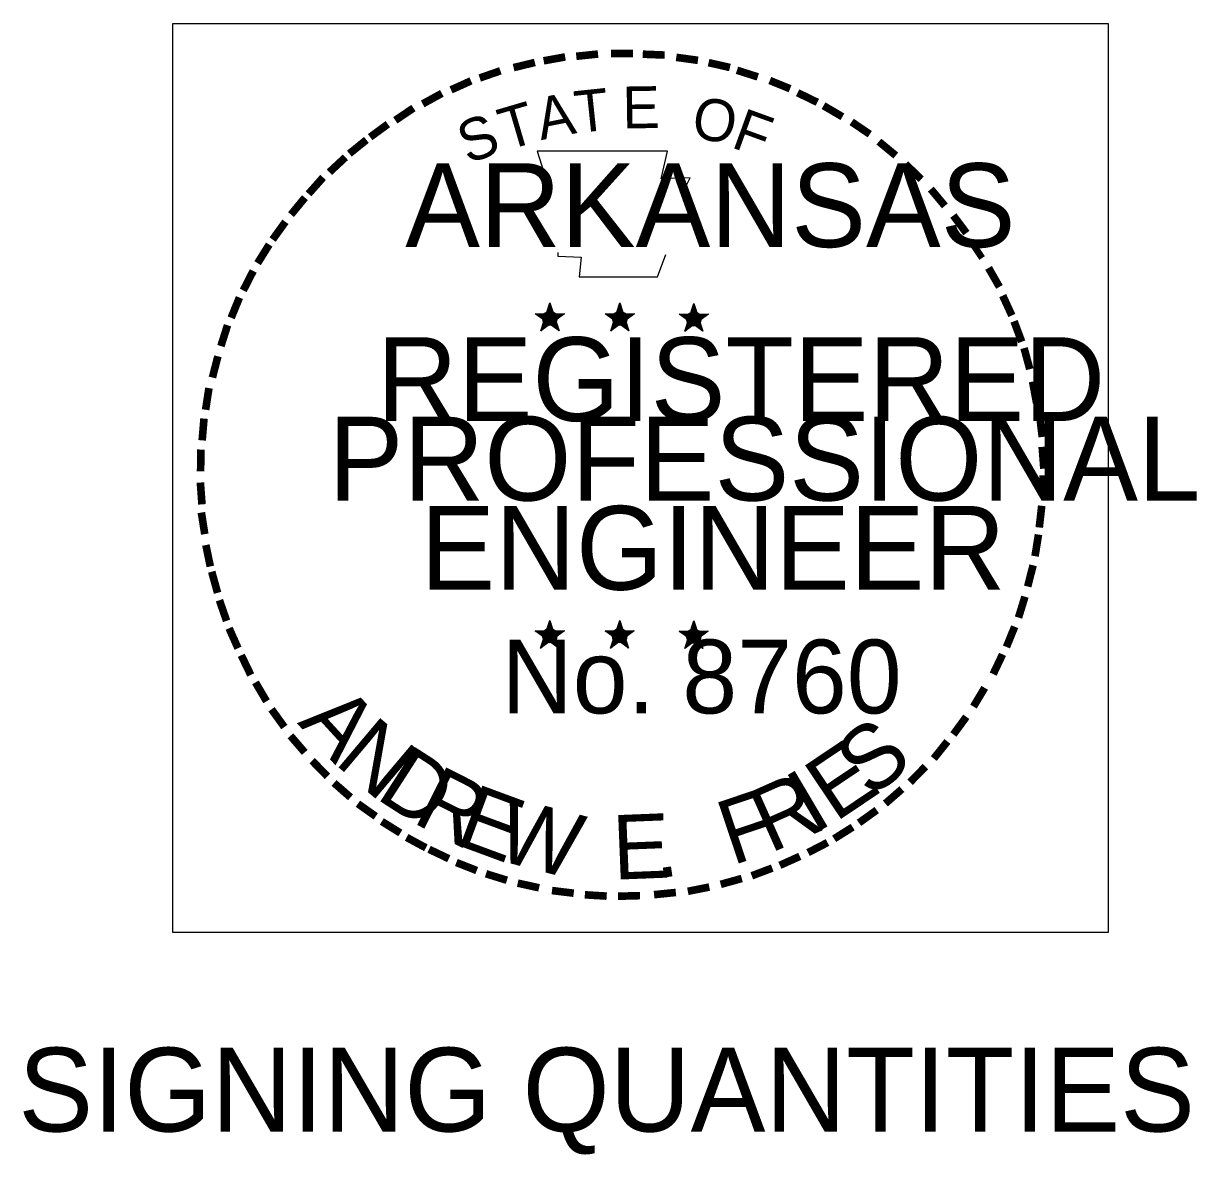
# Model space of a CAD drawing. Extents: x 1226631 to 1228126, y 151309 to 152305.
# Drawn here: x 1227951.4 to 1228126.5, y 151309.4 to 151478.1 of the extents above; entities that cross this region are included whole.
import ezdxf

# ---------------------------------------------------------------- set-up
doc = ezdxf.new("R2010")
doc.units = 0
for name, color, linetype in [('R_Border Notes', 7, 'Continuous'), ('R_Border PE', 7, 'Continuous'), ('R_Border Prem', 7, 'Continuous')]:
    doc.layers.add(name, color=color, linetype=linetype)

msp = doc.modelspace()

# ---------------------------------------------------------------- linework, layer by layer
at = {"layer": 'R_Border PE'}
for p, q in [((1228029.97, 151436.44), (1228029.65, 151434.88)), ((1228029.97, 151436.44), (1228029.72, 151434.81)), ((1228029.97, 151436.44), (1228029.9, 151434.88)), ((1228029.97, 151434.13), (1228029.97, 151436.44)), ((1228029.97, 151436.44), (1228030.4, 151434.81)), ((1228029.97, 151436.44), (1228030.28, 151434.88)), ((1228029.97, 151436.44), (1228030.15, 151434.88)), ((1228040.4, 151436.44), (1228040.09, 151434.88)), ((1228040.4, 151436.44), (1228040.15, 151434.81)), ((1228040.4, 151436.44), (1228040.28, 151434.88)), ((1228040.4, 151434.13), (1228040.4, 151436.44)), ((1228040.4, 151436.44), (1228040.84, 151434.81)), ((1228040.4, 151436.44), (1228040.72, 151434.88)), ((1228040.4, 151436.44), (1228040.53, 151434.88)), ((1228051.47, 151436.31), (1228051.09, 151434.81)), ((1228051.47, 151436.31), (1228051.22, 151434.75)), ((1228051.47, 151436.31), (1228051.34, 151434.75)), ((1228051.47, 151434.06), (1228051.47, 151436.31)), ((1228051.47, 151436.31), (1228051.9, 151434.75)), ((1228051.47, 151436.31), (1228051.78, 151434.75)), ((1228051.47, 151436.31), (1228051.59, 151434.81)), ((1228027.78, 151434.81), (1228029.97, 151434.13)), ((1228027.78, 151434.81), (1228029.4, 151434.69)), ((1228027.78, 151434.81), (1228029.4, 151434.56)), ((1228027.78, 151434.81), (1228029.34, 151434.44)), ((1228027.78, 151434.81), (1228029.34, 151434.19)), ((1228027.78, 151434.81), (1228029.28, 151434.06)), ((1228027.78, 151434.81), (1228029.28, 151433.94)), ((1228028.65, 151432.25), (1228029.97, 151434.13)), ((1228028.65, 151432.25), (1228029.34, 151434)), ((1228032.15, 151434.81), (1228029.97, 151434.13)), ((1228031.34, 151432.25), (1228029.97, 151434.13)), ((1228032.15, 151434.81), (1228030.22, 151434.69)), ((1228032.15, 151434.81), (1228030.34, 151434.5)), ((1228032.15, 151434.81), (1228030.34, 151434.38)), ((1228031.34, 151432.25), (1228030.47, 151434.06)), ((1228031.34, 151432.25), (1228030.59, 151434.13)), ((1228032.15, 151434.81), (1228030.78, 151434.25)), ((1228032.15, 151434.81), (1228030.9, 151434.19)), ((1228032.15, 151434.81), (1228030.97, 151434.13)), ((1228038.22, 151434.81), (1228040.4, 151434.13)), ((1228038.22, 151434.81), (1228039.84, 151434.69)), ((1228038.22, 151434.81), (1228039.84, 151434.56)), ((1228038.22, 151434.81), (1228039.78, 151434.44)), ((1228038.22, 151434.81), (1228039.72, 151434.19)), ((1228038.22, 151434.81), (1228039.72, 151434.06)), ((1228038.22, 151434.81), (1228039.72, 151433.94)), ((1228039.09, 151432.25), (1228040.4, 151434.13)), ((1228039.09, 151432.25), (1228039.78, 151434)), ((1228042.59, 151434.81), (1228040.4, 151434.13)), ((1228041.78, 151432.25), (1228040.4, 151434.13)), ((1228042.59, 151434.81), (1228040.65, 151434.69)), ((1228042.59, 151434.81), (1228040.78, 151434.5)), ((1228042.59, 151434.81), (1228040.78, 151434.38)), ((1228041.78, 151432.25), (1228040.9, 151434.06)), ((1228041.78, 151432.25), (1228041.03, 151434.13)), ((1228042.59, 151434.81), (1228041.22, 151434.25)), ((1228042.59, 151434.81), (1228041.34, 151434.19)), ((1228042.59, 151434.81), (1228041.4, 151434.13)), ((1228049.28, 151434.75), (1228051.47, 151434.06)), ((1228049.28, 151434.75), (1228050.9, 151434.56)), ((1228049.28, 151434.75), (1228050.84, 151434.44)), ((1228049.28, 151434.75), (1228050.84, 151434.38)), ((1228049.28, 151434.75), (1228050.78, 151434.13)), ((1228049.28, 151434.75), (1228050.78, 151434)), ((1228049.28, 151434.75), (1228050.78, 151433.88)), ((1228050.09, 151432.19), (1228051.47, 151434.06)), ((1228053.65, 151434.75), (1228051.47, 151434.06)), ((1228052.78, 151432.19), (1228051.47, 151434.06)), ((1228053.65, 151434.75), (1228051.72, 151434.63)), ((1228053.65, 151434.75), (1228051.84, 151434.44)), ((1228053.65, 151434.75), (1228051.84, 151434.31)), ((1228052.78, 151432.19), (1228051.97, 151434)), ((1228052.78, 151432.19), (1228052.09, 151434)), ((1228053.65, 151434.75), (1228052.28, 151434.19)), ((1228053.65, 151434.75), (1228052.34, 151434.13)), ((1228053.65, 151434.75), (1228052.47, 151434.06)), ((1228028.65, 151432.25), (1228029.4, 151433.81)), ((1228028.65, 151432.25), (1228029.53, 151433.75)), ((1228028.65, 151432.25), (1228029.97, 151433.63)), ((1228028.65, 151432.25), (1228029.72, 151433.56)), ((1228028.65, 151432.25), (1228030.03, 151433.44)), ((1228031.34, 151432.25), (1228029.97, 151433.63)), ((1228031.34, 151432.25), (1228029.97, 151433.44)), ((1228031.34, 151432.25), (1228030.22, 151433.56)), ((1228031.34, 151432.25), (1228030.4, 151433.81)), ((1228039.09, 151432.25), (1228039.84, 151433.81)), ((1228039.09, 151432.25), (1228039.97, 151433.75)), ((1228039.09, 151432.25), (1228040.4, 151433.63)), ((1228039.09, 151432.25), (1228040.15, 151433.56)), ((1228039.09, 151432.25), (1228040.47, 151433.44)), ((1228041.78, 151432.25), (1228040.4, 151433.63)), ((1228041.78, 151432.25), (1228040.4, 151433.44)), ((1228041.78, 151432.25), (1228040.65, 151433.56)), ((1228041.78, 151432.25), (1228040.84, 151433.81)), ((1228050.09, 151432.19), (1228050.84, 151433.94)), ((1228050.09, 151432.19), (1228050.9, 151433.75)), ((1228050.09, 151432.19), (1228051.03, 151433.69)), ((1228050.09, 151432.19), (1228051.47, 151433.56)), ((1228050.09, 151432.19), (1228051.22, 151433.5)), ((1228050.09, 151432.19), (1228051.53, 151433.38)), ((1228052.78, 151432.19), (1228051.47, 151433.56)), ((1228052.78, 151432.19), (1228051.47, 151433.38)), ((1228052.78, 151432.19), (1228051.72, 151433.5)), ((1228052.78, 151432.19), (1228051.9, 151433.75)), ((1228029.97, 151389.06), (1228029.59, 151387.56)), ((1228029.97, 151389.06), (1228029.72, 151387.5)), ((1228029.97, 151389.06), (1228029.84, 151387.5)), ((1228029.97, 151386.81), (1228029.97, 151389.06)), ((1228029.97, 151389.06), (1228030.4, 151387.5)), ((1228029.97, 151389.06), (1228030.28, 151387.5)), ((1228029.97, 151389.06), (1228030.09, 151387.5)), ((1228040.4, 151389.06), (1228040.03, 151387.56)), ((1228040.4, 151389.06), (1228040.15, 151387.5)), ((1228040.4, 151389.06), (1228040.28, 151387.5)), ((1228040.4, 151386.81), (1228040.4, 151389.06)), ((1228040.4, 151389.06), (1228040.78, 151387.5)), ((1228040.4, 151389.06), (1228040.72, 151387.5)), ((1228040.4, 151389.06), (1228040.53, 151387.5)), ((1228051.47, 151389), (1228051.09, 151387.44)), ((1228051.47, 151389), (1228051.22, 151387.44)), ((1228051.47, 151389), (1228051.34, 151387.44)), ((1228051.47, 151386.75), (1228051.47, 151389)), ((1228051.47, 151389), (1228051.84, 151387.44)), ((1228051.47, 151389), (1228051.78, 151387.44)), ((1228051.47, 151389), (1228051.59, 151387.44)), ((1228027.78, 151387.5), (1228029.97, 151386.81)), ((1228027.78, 151387.5), (1228029.4, 151387.31)), ((1228027.78, 151387.5), (1228029.34, 151387.19)), ((1228027.78, 151387.5), (1228029.34, 151387.13)), ((1228027.78, 151387.5), (1228029.28, 151386.88)), ((1228027.78, 151387.5), (1228029.28, 151386.75)), ((1228027.78, 151387.5), (1228029.28, 151386.63)), ((1228028.59, 151384.94), (1228029.97, 151386.81)), ((1228032.15, 151387.5), (1228029.97, 151386.81)), ((1228031.28, 151384.94), (1228029.97, 151386.81)), ((1228032.15, 151387.5), (1228030.22, 151387.38)), ((1228032.15, 151387.5), (1228030.34, 151387.19)), ((1228032.15, 151387.5), (1228030.34, 151387.06)), ((1228031.28, 151384.94), (1228030.4, 151386.75)), ((1228031.28, 151384.94), (1228030.59, 151386.75)), ((1228032.15, 151387.5), (1228030.72, 151386.94)), ((1228032.15, 151387.5), (1228030.84, 151386.88)), ((1228032.15, 151387.5), (1228030.97, 151386.75)), ((1228038.22, 151387.5), (1228040.4, 151386.81)), ((1228038.22, 151387.5), (1228039.78, 151387.31)), ((1228038.22, 151387.5), (1228039.78, 151387.19)), ((1228038.22, 151387.5), (1228039.78, 151387.13)), ((1228038.22, 151387.5), (1228039.72, 151386.88)), ((1228038.22, 151387.5), (1228039.72, 151386.75)), ((1228038.22, 151387.5), (1228039.72, 151386.63)), ((1228039.03, 151384.94), (1228040.4, 151386.81)), ((1228042.53, 151387.5), (1228040.4, 151386.81)), ((1228041.72, 151384.94), (1228040.4, 151386.81)), ((1228042.53, 151387.5), (1228040.65, 151387.38)), ((1228042.53, 151387.5), (1228040.78, 151387.19)), ((1228042.53, 151387.5), (1228040.78, 151387.06)), ((1228041.72, 151384.94), (1228040.84, 151386.75)), ((1228041.72, 151384.94), (1228041.03, 151386.75)), ((1228042.53, 151387.5), (1228041.15, 151386.94)), ((1228042.53, 151387.5), (1228041.28, 151386.88)), ((1228042.53, 151387.5), (1228041.4, 151386.75)), ((1228049.28, 151387.44), (1228051.47, 151386.75)), ((1228049.28, 151387.44), (1228050.84, 151387.25)), ((1228049.28, 151387.44), (1228050.84, 151387.13)), ((1228049.28, 151387.44), (1228050.78, 151387)), ((1228049.28, 151387.44), (1228050.78, 151386.81)), ((1228049.28, 151387.44), (1228050.72, 151386.63)), ((1228049.28, 151387.44), (1228050.72, 151386.5)), ((1228050.09, 151384.88), (1228051.47, 151386.75)), ((1228053.59, 151387.44), (1228051.47, 151386.75)), ((1228052.78, 151384.88), (1228051.47, 151386.75)), ((1228053.59, 151387.44), (1228051.72, 151387.31)), ((1228053.59, 151387.44), (1228051.84, 151387.13)), ((1228053.59, 151387.44), (1228051.84, 151387)), ((1228053.59, 151387.44), (1228052.22, 151386.88)), ((1228053.59, 151387.44), (1228052.34, 151386.75)), ((1228053.59, 151387.44), (1228052.4, 151386.69)), ((1228028.59, 151384.94), (1228029.34, 151386.69)), ((1228028.59, 151384.94), (1228029.4, 151386.44)), ((1228028.59, 151384.94), (1228029.53, 151386.38)), ((1228028.59, 151384.94), (1228029.97, 151386.31)), ((1228028.59, 151384.94), (1228029.72, 151386.25)), ((1228028.59, 151384.94), (1228029.97, 151386.13)), ((1228031.28, 151384.94), (1228029.9, 151386.13)), ((1228031.28, 151384.94), (1228029.97, 151386.25)), ((1228031.28, 151384.94), (1228030.15, 151386.25)), ((1228031.28, 151384.94), (1228030.4, 151386.5)), ((1228039.03, 151384.94), (1228039.78, 151386.69)), ((1228039.03, 151384.94), (1228039.84, 151386.44)), ((1228039.03, 151384.94), (1228039.97, 151386.38)), ((1228039.03, 151384.94), (1228040.4, 151386.31)), ((1228039.03, 151384.94), (1228040.15, 151386.25)), ((1228039.03, 151384.94), (1228040.4, 151386.13)), ((1228041.72, 151384.94), (1228040.34, 151386.13)), ((1228041.72, 151384.94), (1228040.4, 151386.25)), ((1228041.72, 151384.94), (1228040.59, 151386.25)), ((1228041.72, 151384.94), (1228040.84, 151386.5)), ((1228050.09, 151384.88), (1228050.78, 151386.63)), ((1228050.09, 151384.88), (1228050.84, 151386.38)), ((1228050.09, 151384.88), (1228051.03, 151386.31)), ((1228050.09, 151384.88), (1228051.22, 151386.19)), ((1228050.09, 151384.88), (1228051.4, 151386.19)), ((1228050.09, 151384.88), (1228051.47, 151386.06)), ((1228052.78, 151384.88), (1228051.4, 151386.19)), ((1228052.78, 151384.88), (1228051.4, 151386)), ((1228052.78, 151384.88), (1228051.65, 151386.19)), ((1228052.78, 151384.88), (1228051.84, 151386.38)), ((1228052.78, 151384.88), (1228051.9, 151386.69)), ((1228052.78, 151384.88), (1228052.03, 151386.69))]:
    msp.add_line(p, q, dxfattribs=at)
for points in [[(1228028.09, 151459.06), (1228029.72, 151453.88)], [(1228050.03, 151453.31), (1228050.9, 151455.06), (1228046.59, 151454.94), (1228047.53, 151459.06), (1228028.09, 151459.06)], [(1228031.15, 151443.94), (1228031.15, 151443.38), (1228034.65, 151443.25), (1228034.34, 151440.31), (1228046.03, 151440.31), (1228047.28, 151443.63)], [(1228029.97, 151436.44), (1228031.34, 151432.25), (1228027.78, 151434.81), (1228032.15, 151434.81), (1228028.65, 151432.25), (1228029.97, 151436.44)], [(1228040.4, 151436.44), (1228041.78, 151432.25), (1228038.22, 151434.81), (1228042.59, 151434.81), (1228039.09, 151432.25), (1228040.4, 151436.44)], [(1228051.47, 151436.31), (1228052.78, 151432.19), (1228049.28, 151434.75), (1228053.65, 151434.75), (1228050.09, 151432.19), (1228051.47, 151436.31)], [(1228029.97, 151389.06), (1228031.28, 151384.94), (1228027.78, 151387.5), (1228032.15, 151387.5), (1228028.59, 151384.94), (1228029.97, 151389.06)], [(1228040.4, 151389.06), (1228041.72, 151384.94), (1228038.22, 151387.5), (1228042.53, 151387.5), (1228039.03, 151384.94), (1228040.4, 151389.06)], [(1228051.47, 151389), (1228052.78, 151384.88), (1228049.28, 151387.44), (1228053.59, 151387.44), (1228050.09, 151384.88), (1228051.47, 151389)]]:
    msp.add_lwpolyline(points, dxfattribs=at)
for centre, radius in [((1228029.99, 151434.12), 1.08), ((1228029.99, 151434.12), 0.975), ((1228029.99, 151434.12), 0.904), ((1228029.99, 151434.12), 0.83), ((1228029.99, 151434.12), 0.723), ((1228029.99, 151434.12), 0.672), ((1228029.99, 151434.12), 0.619), ((1228029.99, 151434.12), 0.533), ((1228029.99, 151434.12), 0.467), ((1228029.99, 151434.12), 0.388), ((1228029.99, 151434.12), 0.31), ((1228029.99, 151434.12), 0.231), ((1228029.99, 151434.12), 0.185), ((1228029.99, 151434.12), 0.0901), ((1228040.42, 151434.12), 1.08), ((1228040.42, 151434.12), 0.975), ((1228040.42, 151434.12), 0.904), ((1228040.42, 151434.12), 0.83), ((1228040.42, 151434.12), 0.723), ((1228040.42, 151434.12), 0.672), ((1228040.42, 151434.12), 0.619), ((1228040.42, 151434.12), 0.533), ((1228040.42, 151434.12), 0.467), ((1228040.42, 151434.12), 0.388), ((1228040.42, 151434.12), 0.31), ((1228040.42, 151434.12), 0.231), ((1228040.42, 151434.12), 0.185), ((1228040.42, 151434.12), 0.0901), ((1228051.46, 151434.05), 1.08), ((1228051.46, 151434.05), 0.975), ((1228051.46, 151434.05), 0.904), ((1228051.46, 151434.05), 0.83), ((1228051.46, 151434.05), 0.723), ((1228051.46, 151434.05), 0.672), ((1228051.46, 151434.05), 0.619), ((1228051.46, 151434.05), 0.533), ((1228051.46, 151434.05), 0.467), ((1228051.46, 151434.05), 0.388), ((1228051.46, 151434.05), 0.31), ((1228051.46, 151434.05), 0.231), ((1228051.46, 151434.05), 0.185), ((1228051.46, 151434.05), 0.0901), ((1228029.96, 151386.79), 1.08), ((1228029.96, 151386.79), 0.975), ((1228029.96, 151386.79), 0.904), ((1228029.96, 151386.79), 0.83), ((1228029.96, 151386.79), 0.723), ((1228029.96, 151386.79), 0.672), ((1228029.96, 151386.79), 0.619), ((1228029.96, 151386.79), 0.533), ((1228029.96, 151386.79), 0.467), ((1228029.96, 151386.79), 0.388), ((1228029.96, 151386.79), 0.31), ((1228029.96, 151386.79), 0.231), ((1228029.96, 151386.79), 0.185), ((1228029.96, 151386.79), 0.0901), ((1228040.39, 151386.79), 1.08), ((1228040.39, 151386.79), 0.975), ((1228040.39, 151386.79), 0.904), ((1228040.39, 151386.79), 0.83), ((1228040.39, 151386.79), 0.723), ((1228040.39, 151386.79), 0.672), ((1228040.39, 151386.79), 0.619), ((1228040.39, 151386.79), 0.533), ((1228040.39, 151386.79), 0.467), ((1228040.39, 151386.79), 0.388), ((1228040.39, 151386.79), 0.31), ((1228040.39, 151386.79), 0.231), ((1228040.39, 151386.79), 0.185), ((1228040.39, 151386.79), 0.0901), ((1228051.44, 151386.72), 1.08), ((1228051.44, 151386.72), 0.975), ((1228051.44, 151386.72), 0.904), ((1228051.44, 151386.72), 0.83), ((1228051.44, 151386.72), 0.723), ((1228051.44, 151386.72), 0.672), ((1228051.44, 151386.72), 0.619), ((1228051.44, 151386.72), 0.533), ((1228051.44, 151386.72), 0.467), ((1228051.44, 151386.72), 0.388), ((1228051.44, 151386.72), 0.31), ((1228051.44, 151386.72), 0.231), ((1228051.44, 151386.72), 0.185), ((1228051.44, 151386.72), 0.0901)]:
    msp.add_circle(centre, radius, dxfattribs=at)
at = {"layer": 'R_Border Prem'}
msp.add_lwpolyline([(1227973.75, 151478.11), (1228113.25, 151478.11), (1228113.25, 151342.49), (1227973.75, 151342.49)], close=True, dxfattribs=at)

# ---------------------------------------------------------------- texts
at = {"layer": 'R_Border Notes'}
msp.add_text('SIGNING QUANTITIES', height=12.5, dxfattribs=at).set_placement((1227950.68, 151312.82))
at = {"layer": 'R_Border PE'}
for s, height, rotation, p in [('-', 10, 13.6302, (1228024.9, 151467.63)), ('-', 10, 10.2193, (1228029.15, 151468.63)), ('-', 10, 5.8968, (1228033.72, 151469.31)), ('-', 10, 0.1862, (1228038.53, 151469.75)), ('-', 10, 357.743, (1228043.09, 151469.69)), ('-', 10, 352.1617, (1228047.72, 151469.31)), ('-', 10, 347.2049, (1228052.22, 151468.63)), ('-', 10, 19.1761, (1228020.22, 151466.13)), ('-', 10, 342.3362, (1228056.15, 151467.63)), ('-', 10, 24.3072, (1228016.28, 151464.44)), ('-', 10, 337.8551, (1228060.78, 151466.25)), ('-', 10, 28.7918, (1228012.34, 151462.44)), ('A', 6.25, 11.2132, (1228028.65, 151460.69)), ('T', 6.25, 6.0228, (1228033.97, 151461.75)), ('E', 6.25, 0.8323, (1228040.84, 151462.44)), ('-', 10, 334.1211, (1228064.72, 151464.56)), ('-', 10, 34.0636, (1228008.59, 151460.13)), ('T', 6.25, 16.4036, (1228023.47, 151459.13)), ('O', 6.25, 350.4515, (1228050.9, 151461.13)), ('-', 10, 329.6409, (1228068.34, 151462.81)), ('S', 6.25, 21.594, (1228017.78, 151457.06)), ('F', 6.25, 340.0707, (1228056.84, 151459.69)), ('-', 10, 325.8627, (1228072.34, 151460.56)), ('-', 10, 36.2317, (1228004.97, 151457.69)), ('-', 10, 38.9507, (1228002.03, 151455.31)), ('-', 10, 320.5297, (1228076.15, 151457.88)), ('-', 10, 42.9622, (1227999.28, 151452.69)), ('-', 10, 315.5786, (1228079.9, 151454.81)), ('-', 10, 48.423, (1227996.47, 151449.69)), ('-', 10, 309.8797, (1228083.47, 151451.38)), ('-', 10, 50.6142, (1227993.97, 151446.69)), ('-', 10, 306.6522, (1228086.72, 151447.63)), ('-', 10, 54.2325, (1227991.4, 151443.13)), ('-', 10, 58.0706, (1227989.34, 151439.81)), ('-', 8.75, 303.6753, (1228089.78, 151444.06)), ('-', 10, 62.8713, (1227987.4, 151436)), ('-', 10, 299.6684, (1228091.78, 151440.25)), ('-', 10, 294.6628, (1228093.78, 151436.44)), ('-', 10, 67.7743, (1227985.78, 151432.19)), ('-', 10, 72.3945, (1227984.4, 151428.25)), ('-', 10, 290.5728, (1228095.4, 151432.88)), ('-', 10, 285.1233, (1228096.84, 151429.25)), ('-', 10, 75.461, (1227983.22, 151423.75)), ('-', 10, 81.2013, (1227982.34, 151419.31)), ('-', 10, 280.5493, (1228098.09, 151424.56)), ('-', 10, 85.1863, (1227981.9, 151415)), ('-', 10, 276.5962, (1228099.15, 151419.81)), ('-', 10, 274.3301, (1228099.53, 151415.25)), ('-', 10, 89.0622, (1227981.72, 151410.63)), ('-', 10, 94.1959, (1227981.97, 151406.06)), ('-', 10, 269.9407, (1228099.72, 151411.31)), ('-', 10, 263.5172, (1228099.59, 151407.19)), ('-', 10, 98.9479, (1227982.4, 151401.94)), ('-', 10, 260.9953, (1228099.15, 151403.06)), ('-', 10, 101.7149, (1227983.22, 151397.31)), ('-', 10, 255.7626, (1228098.47, 151398.81)), ('-', 10, 105.4578, (1227984.28, 151393.63)), ('-', 10, 109.0874, (1227985.59, 151389.69)), ('-', 10, 252.8681, (1228097.34, 151394.31)), ('-', 10, 114.0643, (1227987.22, 151385.94)), ('-', 10, 247.8887, (1228095.97, 151390.13)), ('-', 10, 115.7289, (1227989.09, 151382.06)), ('-', 10, 244.6197, (1228094.28, 151386.19)), ('-', 10, 120.4471, (1227991.34, 151378.44)), ('-', 10, 239.0712, (1228091.84, 151381.5)), ('A', 9.62, 312.4727, (1227992.22, 151373.74)), ('-', 10, 125.8934, (1227993.84, 151374.94)), ('-', 10, 233.8452, (1228089.34, 151377.44)), ('N', 9.62, 319.8362, (1227997.65, 151367.81)), ('S', 9.62, 39.723, (1228077.88, 151362.35)), ('-', 10, 130.7181, (1227996.72, 151371.44)), ('E', 9.62, 33.8878, (1228072.54, 151358.86)), ('-', 10, 231.2538, (1228086.65, 151373.88)), ('D', 9.62, 327.1996, (1228003.8, 151362.63)), ('-', 10, 134.2238, (1227999.97, 151368.06)), ('-', 10, 225.7653, (1228083.65, 151370.38)), ('R', 9.62, 333.1738, (1228009.24, 151359.02)), ('R', 9.62, 24.0235, (1228062.81, 151354.26)), ('I', 9.62, 30.5534, (1228069.34, 151357.12)), ('-', 10, 138.9338, (1228003.22, 151365.19)), ('E', 9.62, 339.7037, (1228015.58, 151355.76)), ('-', 10, 221.0851, (1228080.4, 151367.19)), ('W', 9.62, 345.5389, (1228021.53, 151353.47)), ('F', 9.62, 18.6051, (1228057.16, 151352.47)), ('-', 10, 144.6463, (1228006.72, 151362.63)), ('-', 10, 215.7363, (1228076.97, 151364.25)), ('-', 10, 148.0898, (1228010.22, 151360.31)), ('E', 9.62, 2.2804, (1228039.5, 151350.37)), ('-', 10, 151.5704, (1228013.84, 151358.25)), ('-', 10, 212.2491, (1228073.59, 151361.81)), ('-', 10, 154.6002, (1228017.09, 151356.75)), ('-', 10, 207.3568, (1228070.15, 151359.63)), ('-', 10, 204.2516, (1228066.22, 151357.63)), ('-', 10, 158.5612, (1228021.03, 151355.13)), ('-', 10, 162.7983, (1228025.28, 151353.81)), ('.', 9.62, 8.1156, (1228045.88, 151350.54)), ('-', 10, 200.7184, (1228062.34, 151355.94)), ('-', 10, 167.5555, (1228029.78, 151352.81)), ('-', 10, 195.4743, (1228058.15, 151354.44)), ('-', 10, 173.1155, (1228034.59, 151352.13)), ('-', 10, 176.5183, (1228039.28, 151351.75)), ('-', 10, 181.5918, (1228043.9, 151351.88)), ('-', 10, 185.8167, (1228048.97, 151352.38)), ('-', 10, 191.2858, (1228053.59, 151353.19))]:
    msp.add_text(s, height=height, rotation=rotation, dxfattribs=at).set_placement(p)
for s, height, p in [('ARKANSAS', 12.5, (1228008.4, 151444.75)), ('REGISTERED', 12.5, (1228004.15, 151418.81)), ('PROFESSIONAL', 12.4999, (1227996.97, 151406.94)), ('ENGINEER', 12.5, (1228010.65, 151393.63)), ('No. 8760', 11, (1228022.76, 151375.19))]:
    msp.add_text(s, height=height, dxfattribs=at).set_placement(p)

doc.saveas('drawing.dxf')
